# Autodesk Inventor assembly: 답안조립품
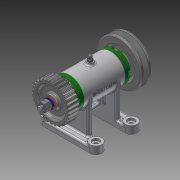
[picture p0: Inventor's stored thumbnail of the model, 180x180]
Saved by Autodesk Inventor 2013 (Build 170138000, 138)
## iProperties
Created: 2015-11
Part Number: 답안조립품
Document SubType Name: Assembly
Designer: cad10
Author: cad10
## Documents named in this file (16)
- C:\Documents and Settings\cad10\바탕 화면\451110V1008\답안조립품.iam
- C:\Documents and Settings\cad10\바탕 화면\451110V1008\본체.ipt
- C:\Documents and Settings\cad10\바탕 화면\451110V1008\베어링 15 x 32 x 9.ipt
- C:\Documents and Settings\cad10\바탕 화면\451110V1008\커버.ipt
- C:\Documents and Settings\cad10\바탕 화면\451110V1008\축.ipt
- C:\Documents and Settings\cad10\바탕 화면\451110V1008\볼트 M4 x 12.ipt
- C:\Documents and Settings\cad10\바탕 화면\451110V1008\오일 실 15 25 7.ipt
- C:\Documents and Settings\cad10\바탕 화면\451110V1008\니플 M 6 x 0.75.ipt
- C:\Documents and Settings\cad10\바탕 화면\451110V1008\키 3 x 3 x 12.ipt
- C:\Documents and Settings\cad10\바탕 화면\451110V1008\와셔 6x11.5.ipt
- C:\Documents and Settings\cad10\바탕 화면\451110V1008\볼트 M 6 x 8.ipt
- C:\Documents and Settings\cad10\바탕 화면\451110V1008\V벨트풀리.ipt
- C:\Documents and Settings\cad10\바탕 화면\451110V1008\스퍼기어.ipt
- C:\Documents and Settings\cad10\바탕 화면\451110V1008\와셔 8x17.ipt
- C:\Documents and Settings\cad10\바탕 화면\451110V1008\스프링와셔 8.ipt
- C:\Documents and Settings\cad10\바탕 화면\451110V1008\너트 M 8.ipt
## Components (11 placed, 3 different names)
1. KS B 2023 6002 - 15 x 32 x 9:1
2. KS B 2023 6002 - 15 x 32 x 9:2
3. V벨트풀리:1 — 각도:3
4. ISO 4762 M4 x 12:2
5. ISO 4762 M4 x 12:3
6. ISO 4762 M4 x 12:4
7. ISO 4762 M4 x 12:5
8. ISO 4762 M4 x 12:1
9. ISO 4762 M4 x 12:6
10. ISO 4762 M4 x 12:7
11. ISO 4762 M4 x 12:8
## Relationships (1: Angle 1)
- 각도:3 [Angle]: V벨트풀리:1
